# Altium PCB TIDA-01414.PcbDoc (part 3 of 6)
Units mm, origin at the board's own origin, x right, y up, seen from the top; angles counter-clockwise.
Board outline 400 x 135 mm, 4 copper layers (Top Copper, Copper Layer 2, Copper Layer 3, Bottom Copper), stack 1.567 mm thick; 835 components, 519 nets, 2420 pads, 2045 vias.
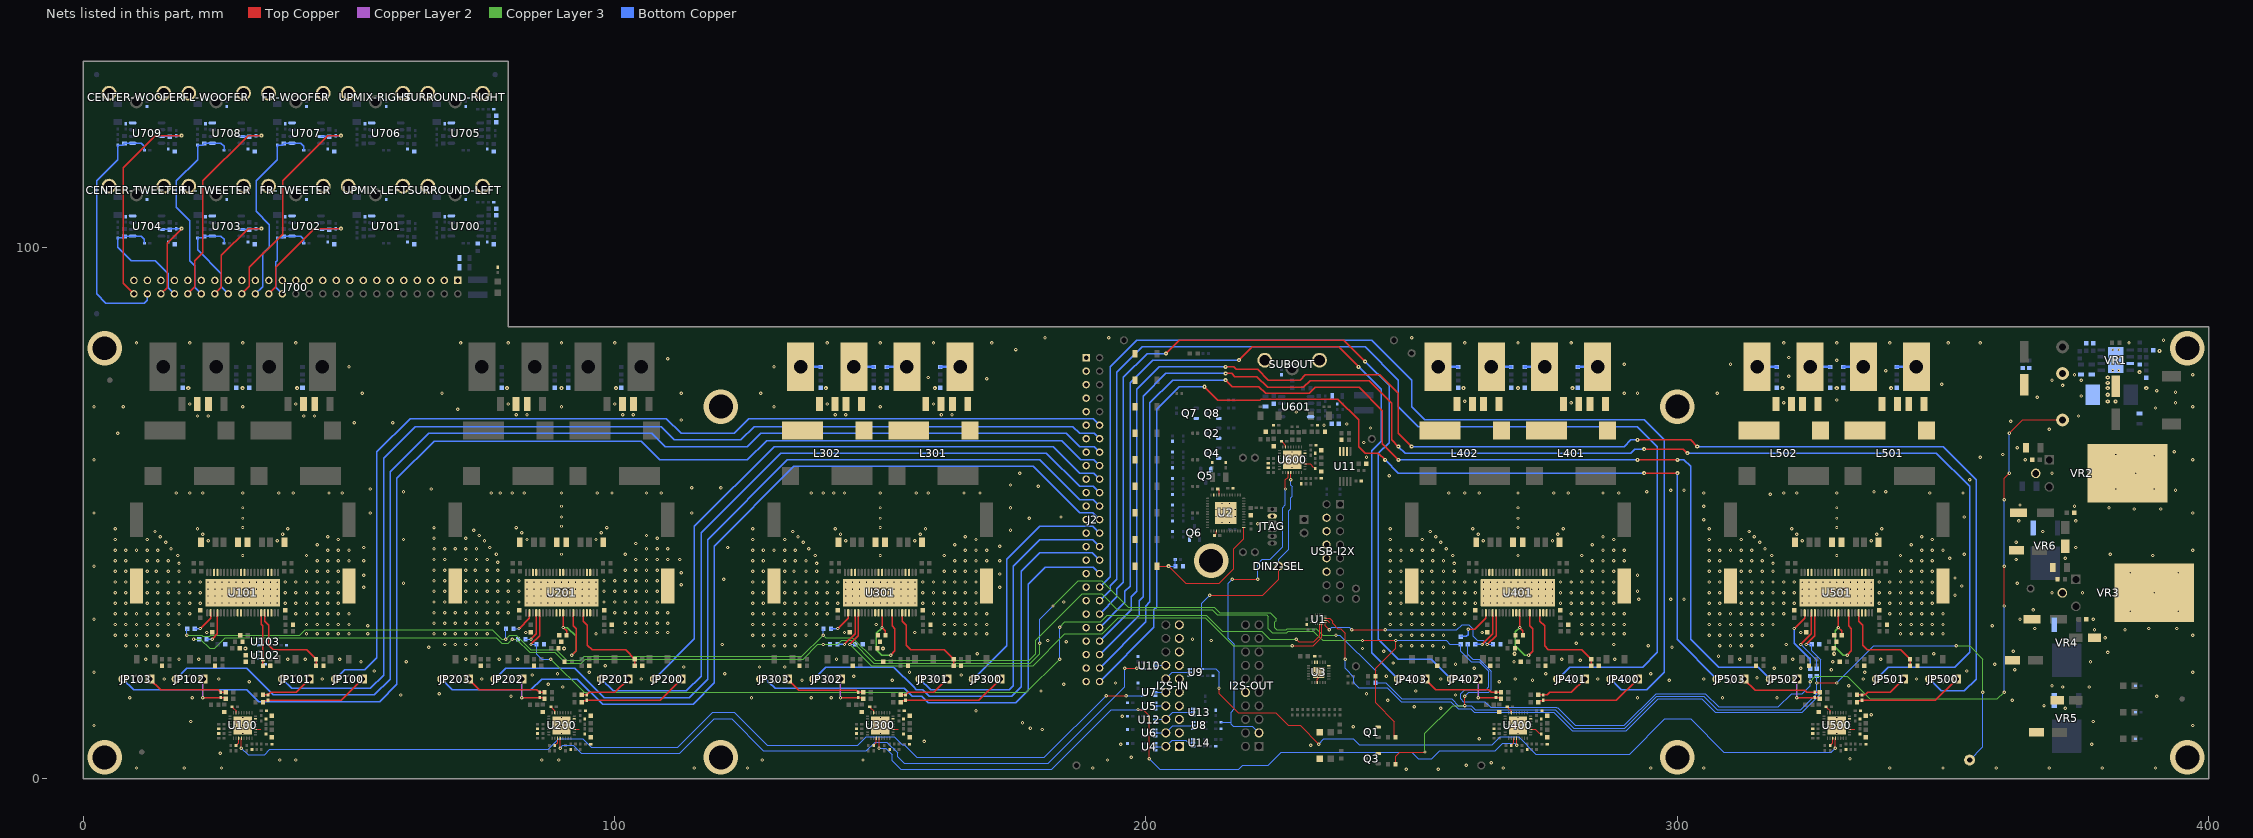
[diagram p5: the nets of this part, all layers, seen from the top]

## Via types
v1: diameter 0.635, hole 0.254, Top Copper to Bottom Copper, tented both sides, 1429 vias
v2: diameter 0.762, hole 0.254, Top Copper to Bottom Copper, tented both sides, 311 vias
v3: diameter 0.5, hole 0.2, Top Copper to Bottom Copper, 150 vias
v4: diameter 0.5, hole 0.2, Top Copper to Bottom Copper, tented both sides, 124 vias
v5: diameter 0.508, hole 0.254, Top Copper to Bottom Copper, tented both sides, 21 vias
v6: diameter 6.5, hole 4.5, Top Copper to Bottom Copper, tented both sides, 9 vias
v7: diameter 0.889, hole 0.254, Top Copper to Bottom Copper, tented both sides, 1 vias

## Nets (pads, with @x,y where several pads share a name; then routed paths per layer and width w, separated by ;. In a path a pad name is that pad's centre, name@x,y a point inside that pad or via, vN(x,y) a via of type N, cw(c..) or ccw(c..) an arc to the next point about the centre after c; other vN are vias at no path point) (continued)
\AMP-RESET2: R55.1 U1.3 U201.5 | length 174.4
  Top Copper w0.2: v1(228.25,26.25) 228.783,25.717 231.533,25.717 232.7,26.884 U1.3@232.7,29.2
  Top Copper w0.25: v1(84.25,25.25) 85.873,26.873 U201.5@85.873,31.2 U201.5@85.873,31.3
  Copper Layer 3 w0.2: v1(88,22.5) 94.25,16.25 177.5,16.25 v1(183.75,22.5) ; v1(183.75,28.5) 184.75,29.5 191.5,29.5 192.75,30.75 211.375,30.75 214.375,27.75 221.75,27.75 223.25,26.25 v1(228.25,26.25)
  Bottom Copper w0.2: v1(84.25,25.25) R55.1@85.3,25.25 85.3,23.45 86.25,22.5 v1(88,22.5) ; v1(183.75,22.5) v1(183.75,28.5)
\AMP-RESET3: R56.1 U1.4 U301.5 | length 107.4
  Top Copper w0.2: v1(227.5,25) 231.5,25 233.1,26.6 U1.4@233.1,29.2
  Top Copper w0.25: v1(144.25,25.25) 145.872,26.873 U301.5@145.872,31.2 U301.5@145.872,31.3
  Copper Layer 3 w0.2: v1(144.25,25.25) 148.25,21.25 178.75,21.25 184.75,27.25 191.75,27.25 194.75,30.25 211.125,30.25 216.375,25 v1(227.5,25)
  Bottom Copper w0.2: v1(144.25,25.25) R56.1@145.3,25.25
\AMP-RESET4: R57.1 U1.5 U401.5 | length 42.4
  Top Copper w0.2: U1.5@233.7,29.4 233.7,28.8 v1(234.5,28) ; v1(238.75,28) v1(245,28)
  Top Copper w0.25: v1(264.25,25.25) 265.873,26.873 U401.5@265.873,31.2 U401.5@265.873,31.3
  Bottom Copper w0.2: v1(234.5,28) 235,28.5 238.25,28.5 v1(238.75,28) ; v1(245,28) 258.5,28 259.5,29 260.75,29 261.625,28.125 261.625,26.75 262.375,26 263.5,26 v1(264.25,25.25) R57.1@265.3,25.25
\AMP-RESET5: R58.1 U1.7 U501.5 | length 129.5
  Top Copper w0.2: U1.7@233.7,30.2 234.55,30.2 235.125,29.625 235.125,29.25 236.125,28.25 236.625,28.25 237.5,27.375 v1(237.5,22.5)
  Top Copper w0.25: v1(324.25,25.25) 325.873,26.873 U501.5@325.873,31.2 U501.5@325.873,31.3
  Bottom Copper w0.2: v1(237.5,22.5) 237.5,20.75 239.125,19.125 239.125,18 240,17.125 245.375,17.125 248,14.5 257.375,14.5 258.75,13.125 261.125,13.125 261.75,12.5 276.75,12.5 280.25,9 290.375,9 296.375,15 304.625,15 307.125,12.5 323.5,12.5 327,16 327,22.375 325.3,24.075 R58.1@325.3,25.25 v1(324.25,25.25)
\CLIP_OTW: R19.1 R20.2 R21.1 R22.1 R23.1 R24.1 R25.1 TP2.1 | length 477.4
  Top Copper w0.2: v1(240.75,26) v1(247,26) 247,24.5 243.25,20.75 243.25,14.25 246.75,10.75 246.75,7.95 R20.2@246.95,7.75 ; v1(361.5,32.5) v1(361.5,40) ; v1(361.5,52.5) 361.5,56.5 v1(362.5,57.5) ; v1(362.5,65) 365,67.5 TP2.1@372.5,67.5
  Copper Layer 3 w0.2: v1(19.5,27) 22.25,27 22.5,26.75 23.75,26.75 24,27 40.75,27 41.75,28 77,28 78.75,26.25 v1(79.5,26.25) 80.25,27 81.5,27 84.25,24.25 89,24.25 91,22.25 93.5,22.25 94.25,23 135.25,23 v1(139.25,27) 139.75,26.5 144.75,26.5 149,22.25 178,22.25 179.25,23.5 179.25,26 188,34.75 191.625,34.75 194.625,31.75 212.5,31.75 213.438,30.812 222.687,30.812 223,30.5 223,28.25 223.75,27.5 226.5,27.5 226.75,27.75 231.5,27.75 233.25,26 v1(240.75,26) ; v1(325,18.25) 326,19.25 332,19.25 336.25,15 360.25,15 v1(361.5,16.25)
  Bottom Copper w0.2: v1(19.5,27) 19.5,28 R21.1@19.75,28.25 ; v1(79.5,26.25) 79.5,28.2 R22.1@79.55,28.25 ; v1(139.25,27) 139.25,28.2 R23.1@139.3,28.25 ; v1(247,26) 256.5,26 257.2,25.3 R24.1@259.25,25.3 259.25,24 261.25,22 262.684,22 264.5,20.184 264.5,17.25 264,16.75 260,16.75 259.25,16 259.25,15 259.75,14.5 263.75,14.5 264.85,13.4 277.166,13.4 277.266,13.3 277.45,13.3 280.75,10 290,10 296,16 305.25,16 307.75,13.5 319,13.5 321.5,16 323.5,16 325,17.5 v1(325,18.25) R25.1@325,19.3 ; v1(361.5,16.25) v1(361.5,32.5) ; v1(361.5,40) v1(361.5,52.5) ; v1(362.5,57.5) v1(362.5,65)
\CLIP_OTW1: R21.2 U101.2 | length 4.9
  Top Copper w0.25: v1(22,28.25) 23.968,30.218 U101.2@23.968,31.3
  Bottom Copper w0.25: R21.2@20.95,28.25 v1(22,28.25)
\CLIP_OTW2: R22.2 U201.2 | length 4.9
  Top Copper w0.25: v1(82,28.25) 83.968,30.218 U201.2@83.968,31.3
  Bottom Copper w0.2: R22.2@80.95,28.25 v1(82,28.25)
\CLIP_OTW3: R23.2 U301.2 | length 5.2
  Top Copper w0.25: v1(142,28.25) 143.967,30.218 U301.2@143.967,31.3
  Bottom Copper w0.25: R23.2@140.7,28.25 v1(142,28.25)
\CLIP_OTW4: R24.2 U401.2 | length 7.9
  Top Copper w0.25: v1(260.625,28.125) 261.875,28.125 263.968,30.218 U401.2@263.968,31.3
  Bottom Copper w0.25: R24.2@259.25,26.7 259.25,26.75 260.25,26.75 260.625,27.125 v1(260.625,28.125)
\CLIP_OTW5: R25.2 U501.2 | length 12.6
  Top Copper w0.25: v1(322,28.25) 323.968,30.218 U501.2@323.968,31.3
  Bottom Copper w0.25: v1(322,28.25) 322,25.5 325,22.5 R25.2@325,20.75
\FAULT: R27.1 R28.2 R29.1 R30.1 R31.1 R32.1 R33.1 TP1.1 | length 443.6
  Top Copper w0.2: R28.2@246.95,2.75 247,2.8 247,4.25 247.75,5 v1(252.5,5) ; v1(260,13.75) v1(260,15.5) ; v1(326.25,18) v1(330,18)
  Copper Layer 3 w0.2: v1(20.75,26.25) 22,26.25 23.75,24.5 24.75,24.5 26.75,26.5 77.75,26.5 78.75,25.5 80,25.5 v1(80.75,26.25) 81.5,26.25 84,23.75 88.75,23.75 90.75,21.75 93.75,21.75 94.5,22.5 135.5,22.5 138.25,25.25 v1(139.25,25.25) 142,25.25 142.75,26 144.5,26 148.75,21.75 178.25,21.75 180,23.5 v1(180,25.5) ; v1(182.5,32.5) 187.25,37.25 191.625,37.25 196.625,32.25 212.875,32.25 213.875,31.25 223.373,31.25 224.062,30.562 224.063,30.562 224.5,30.125 224.5,29.75 224.25,29.5 224.25,28.375 224.625,28 226.375,28 226.625,28.25 232,28.25 233.25,27 v1(235.75,27) ; v1(252.5,5) 252.5,8.5 257.75,13.75 v1(260,13.75) ; v1(352.5,25) 355,25 357.5,22.5 v1(357.5,16.25)
  Bottom Copper w0.2: v1(20.75,26.25) R29.1@21.8,26.25 R29.1@22,26.25 ; v1(80.75,26.25) R30.1@81.8,26.25 ; v1(139.25,25.25) R31.1@140.55,25.25 ; v1(180,25.5) 180,30 v1(182.5,32.5) ; v1(235.75,27) 236.5,27 243.2,20.3 R27.1@243.2,18 245.125,18 248.125,15 257.5,15 258.75,13.75 v1(260,13.75) 261.25,13.75 262,13 277,13 280.5,9.5 290.125,9.5 296.125,15.5 305,15.5 307.5,13 323.25,13 326.25,16 v1(326.25,18) R33.1@326.25,19.3 ; v1(260,15.5) 260.75,16.25 264.5,16.25 265,16.75 265,20.25 262.75,22.5 261.5,22.5 260.55,23.45 R32.1@260.55,25.25 ; v1(330,18) 337,25 v1(352.5,25) ; TP1.1@355,3.5 357.5,6 v1(357.5,16.25)
\FAULT1: R29.2 U101.4 | length 6.5
  Top Copper w0.25: v1(24.25,26.25) 25.238,27.238 U101.4@25.238,31.2 U101.4@25.238,31.3
  Bottom Copper w0.25: R29.2@23.2,26.25 v1(24.25,26.25)
\FAULT2: R30.2 U201.4 | length 6.5
  Top Copper w0.25: v1(84.25,26.25) 85.238,27.238 U201.4@85.238,31.2 U201.4@85.238,31.3
  Bottom Copper w0.2: R30.2@83.2,26.25 v1(84.25,26.25)
\FAULT3: R31.2 U301.4 | length 8.1
  Top Copper w0.25: v1(143.25,25.25) 145.237,27.238 U301.4@145.237,31.2 U301.4@145.237,31.3
  Bottom Copper w0.25: R31.2@142,25.25 v1(143.25,25.25)
\FAULT4: R32.2 U401.4 | length 8.2
  Top Copper w0.25: v1(263.25,25.25) 265.238,27.238 U401.4@265.238,31.2 U401.4@265.238,31.3
  Bottom Copper w0.25: R32.2@261.95,25.25 v1(263.25,25.25)
\FAULT5: R33.2 U501.4 | length 12.7
  Top Copper w0.25: v1(323.25,25.25) 325.238,27.238 U501.4@325.238,31.2 U501.4@325.238,31.3
  Bottom Copper w0.2: v1(323.25,25.25) 326.25,22.25 R33.2@326.25,20.7 R33.2@326.25,20.625
\RESET: C28.2 R74.1 RESET.1 U2.37 | length 28
  Top Copper w0.2: RESET.1@202.1,40 v2(204.25,40) 207.5,36.75 213.75,36.75 216.5,39.5 216.5,43.25 218.4,45.15 U2.37@218.4,47.25
  Bottom Copper w0.2: v2(204.25,40) C28.2@205.55,40 205.55,41.2 R74.1@205.5,41.25
BCK1: R75.1 U100.27 | length 1.6
  Top Copper w0.2: R75.1@28.75,6.25 29.25,6.75 U100.27@29.25,7.6
BCK2: R76.1 U200.27 | length 1.6
  Top Copper w0.2: R76.1@88.75,6.25 89.25,6.75 U200.27@89.25,7.6
BCK3: R77.1 U300.27 | length 1.6
  Top Copper w0.2: R77.1@148.75,6.25 149.25,6.75 U300.27@149.25,7.6
BCK4: R78.1 U400.27 | length 1.6
  Top Copper w0.2: R78.1@268.75,6.25 269.25,6.75 U400.27@269.25,7.6
BCK5: R79.1 U500.27 | length 1.6
  Top Copper w0.2: R79.1@328.75,6.25 329.25,6.75 U500.27@329.25,7.6
BCK6: I2S-OUT.3 R80.1 U600.27 | length 64.2
  Top Copper w0.2: v1(216.25,37.5) v1(221,37.5) ; v1(226.25,54.5) 226.25,56.25 226.75,56.75 U600.27@226.75,57.6
  Bottom Copper w0.2: R80.1@214.125,10.625 216,10.625 ; v1(216.25,37.5) 215.5,36.75 215.5,26.375 216.625,25.25 216.625,13.125 216,12.5 216,10.25 216.375,9.875 220.005,9.875 I2S-OUT.3@221.27,8.61 ; v1(221,37.5) 221,40.375 221.875,41.25 223.375,41.25 225.75,43.625 225.75,51 226.25,51.5 v1(226.25,54.5)
CENTERTWEETER+: C515.1 C516.1 CT+.1 L501.2 | length 3.8
  Bottom Copper w0.5: C516.1@341.25,77.45 341.3,77.5 CT+.1@345,77.5
CENTERTWEETER-: C526.1 C527.1 CT-.1 L501.3 | length 3.8
  Bottom Copper w0.5: C527.1@331.25,77.45 331.3,77.5 CT-.1@335,77.5
CENTERWOOFER+: C535.1 C536.1 CW+.1 L502.2 | length 3.8
  Bottom Copper w0.5: CW+.1@325,77.5 328.7,77.5 C536.1@328.75,77.45
CENTERWOOFER-: C540.1 C541.1 CW-.1 L502.3 | length 3.8
  Bottom Copper w0.5: CW-.1@315,77.5 318.7,77.5 C541.1@318.75,77.45
CT+: C731.2 J700.44 R704.1 R714.1 U704.1 | length 23.7
  Bottom Copper w0.25: R714.1@11.5,100.75 11.5,101.5 10.905,102.095 U704.1@9.275,102.095 7.795,102.095 7.45,101.75 R704.1@6.5,101.75 6.5,100 9,97.5 13.5,97.5 16,95 16,92.37 J700.44@17.14,91.23
CT-: C741.2 J700.46 R719.1 U704.7 | length 17.8
  Top Copper w0.25: J700.46@14.6,91.23 15.75,92.38 15.75,100.75 v2(18.5,103.5)
  Bottom Copper w0.25: U704.7@14.725,103.365 16.185,103.365 C741.2@16.25,103.3 16.45,103.5 R719.1@17.5,103.5 v2(18.5,103.5)
CW+: C746.2 J700.48 R724.1 R734.1 U709.1 | length 47.5
  Bottom Copper w0.25: R734.1@11.5,118.25 11.5,119 10.905,119.595 7.795,119.595 7.45,119.25 R724.1@6.5,119.25 6.5,116.5 2.5,112.5 2.5,91.25 4.25,89.5 11.5,89.5 12.06,90.06 J700.48@12.06,91.23
CW-: C756.2 J700.50 R739.1 U709.7 | length 42
  Top Copper w0.25: J700.50@9.52,91.23 7.5,93.25 7.5,115 13.5,121 v2(18.5,121)
  Bottom Copper w0.25: U709.7@14.725,120.865 16.185,120.865 C756.2@16.25,120.8 16.45,121 v2(18.5,121)
DAC1L+: C117.1 JP100.1 R101.2 | length 20.5
  Top Copper w0.25: R101.2@33.825,14.375 34.075,14.625 34.625,14.625 C117.1@34.75,14.75 48.54,14.75 JP100.1@52.54,18.75
DAC1L-: C117.2 JP101.1 R103.2 | length 10
  Top Copper w0.25: R103.2@33.825,15.75 C117.2@34.75,15.75 35.25,16.25 40.04,16.25 JP101.1@42.54,18.75
DAC1R+: C121.2 JP102.1 R107.2 | length 7.9
  Top Copper w0.25: v1(22.5,15.25) C121.2@25.875,15.25 26.55,15.25 R107.2@26.8,15
  Copper Layer 2 w0.25: v1(22.5,15.25) JP102.1@22.5,18.71
  Bottom Copper w0.25: JP102.1@22.5,18.71 JP102.1@22.54,18.75
DAC1R-: C121.1 JP103.1 R105.2 | length 15.3
  Top Copper w0.25: JP103.1@12.54,18.75 14.54,16.75 25.375,16.75 C121.1@25.875,16.25 R105.2@26.8,16.25
DAC2L+: C217.1 JP200.1 R201.2 | length 20.5
  Top Copper w0.25: R201.2@93.825,14.375 94.075,14.625 94.625,14.625 C217.1@94.75,14.75 108.54,14.75 JP200.1@112.54,18.75
DAC2L-: C217.2 JP201.1 R203.2 | length 10
  Top Copper w0.25: R203.2@93.825,15.75 C217.2@94.75,15.75 95.25,16.25 100.04,16.25 JP201.1@102.54,18.75
DAC2R+: C221.2 JP202.1 R207.2 | length 7.9
  Top Copper w0.25: v1(82.5,15.25) C221.2@85.875,15.25 86.55,15.25 R207.2@86.8,15
  Copper Layer 2 w0.25: v1(82.5,15.25) JP202.1@82.5,18.71
  Bottom Copper w0.25: JP202.1@82.5,18.71 JP202.1@82.54,18.75
DAC2R-: C221.1 JP203.1 R205.2 | length 15.3
  Top Copper w0.25: JP203.1@72.54,18.75 74.54,16.75 85.375,16.75 C221.1@85.875,16.25 R205.2@86.8,16.25
DAC3L+: C317.1 JP300.1 R301.2 | length 20.5
  Top Copper w0.25: R301.2@153.825,14.375 154.075,14.625 154.625,14.625 C317.1@154.75,14.75 168.54,14.75 JP300.1@172.54,18.75
DAC3L-: C317.2 JP301.1 R303.2 | length 10
  Top Copper w0.25: R303.2@153.825,15.75 C317.2@154.75,15.75 155.25,16.25 160.04,16.25 JP301.1@162.54,18.75
DAC3R+: C321.2 JP302.1 R307.2 | length 7.9
  Top Copper w0.25: v1(142.5,15.25) C321.2@145.875,15.25 146.55,15.25 R307.2@146.8,15
  Copper Layer 2 w0.25: v1(142.5,15.25) JP302.1@142.5,18.71
  Bottom Copper w0.25: JP302.1@142.5,18.71 JP302.1@142.54,18.75
DAC3R-: C321.1 JP303.1 R305.2 | length 15.3
  Top Copper w0.25: JP303.1@132.54,18.75 134.665,16.625 145.5,16.625 C321.1@145.875,16.25 R305.2@146.8,16.25
DAC4L+: C417.1 JP400.1 R401.2 | length 20.5
  Top Copper w0.25: R401.2@273.825,14.375 274.075,14.625 274.625,14.625 C417.1@274.75,14.75 288.54,14.75 JP400.1@292.54,18.75
DAC4L-: C417.2 JP401.1 R403.2 | length 10
  Top Copper w0.25: R403.2@273.825,15.75 C417.2@274.75,15.75 275.375,15.75 275.5,15.75 276,16.25 280.04,16.25 JP401.1@282.54,18.75
DAC4R+: C421.2 JP402.1 R407.2 | length 7.9
  Top Copper w0.25: v1(262.5,15.25) C421.2@265.875,15.25 266.55,15.25 R407.2@266.8,15
  Copper Layer 2 w0.25: v1(262.5,15.25) JP402.1@262.5,18.71
  Bottom Copper w0.25: JP402.1@262.5,18.71 JP402.1@262.54,18.75
DAC4R-: C421.1 JP403.1 R405.2 | length 15.3
  Top Copper w0.25: JP403.1@252.54,18.75 254.54,16.75 264.5,16.75 265,16.25 C421.1@265.875,16.25 R405.2@266.8,16.25
DAC5L+: C517.1 JP500.1 R501.2 | length 20.5
  Top Copper w0.25: R501.2@333.825,14.375 334.075,14.625 334.625,14.625 C517.1@334.75,14.75 348.54,14.75 JP500.1@352.54,18.75
DAC5L-: C517.2 JP501.1 R503.2 | length 10
  Top Copper w0.25: R503.2@333.825,15.75 C517.2@334.75,15.75 335.375,15.75 335.875,16.25 340.04,16.25 JP501.1@342.54,18.75
DAC5R+: C521.2 JP502.1 R507.2 | length 7.9
  Top Copper w0.25: v1(322.5,15.25) C521.2@325.875,15.25 326.55,15.25 R507.2@326.8,15
  Copper Layer 2 w0.25: v1(322.5,15.25) JP502.1@322.5,18.71
  Bottom Copper w0.25: JP502.1@322.5,18.71 JP502.1@322.54,18.75
DAC5R-: C521.1 JP503.1 R505.2 | length 15.3
  Top Copper w0.25: JP503.1@312.54,18.75 314.665,16.625 324,16.625 324.375,16.25 C521.1@325.875,16.25 R505.2@326.8,16.25
DIN0: U5.4 U300.28 U400.28 | length 150.8
  Top Copper w0.2: v1(149.75,5.75) U300.28@149.75,7.6 ; v1(198.5,13) 199.5,13 200.625,11.875 v1(200.625,3.75) ; v1(269.75,6.25) U400.28@269.75,7.6
  Bottom Copper w0.2: v1(149.75,5.75) 151,5.75 152.25,4.5 152.25,3.375 153.875,1.75 182.25,1.75 193.5,13 v1(198.5,13) 195.05,13 195.025,12.975 U5.4@199.5,12.975 ; v1(200.625,3.75) 202.625,1.75 217.5,1.75 218.25,2.5 223,2.5 225.5,5 250,5 251.25,3.75 253.75,3.75 255.25,5.25 265.75,5.25 267.125,6.625 269.375,6.625 v1(269.75,6.25)
DIN1: U7.4 U100.28 | length 186.5
  Top Copper w0.2: v1(29.75,5.75) U100.28@29.75,7.6 ; v1(192.5,15.625) v1(196.25,15.625)
  Bottom Copper w0.2: v1(29.75,5.75) 31,4.5 34.123,4.5 35.123,5.5 87.5,5.5 89.5,7.5 94,7.5 95.625,5.875 111.875,5.875 118.5,12.5 122.5,12.5 128.75,6.25 145.75,6.25 147.375,7.875 152.625,7.875 154.125,6.375 154.5,6.375 156.875,4 180.875,4 v1(192.5,15.625) ; v1(196.25,15.625) 199.475,15.625 U7.4@199.5,15.6
DIN2: DIN2-SEL.2 U9.4 U500.28 U600.28 | length 187.7
  Top Copper w0.2: v1(212,34.5) 222,34.5 225,37.5 DIN2-SEL.2@225,40 ; v1(213.75,17) 213.75,16 217.375,12.375 224.375,12.375 226.75,10 229,10 v1(232.5,6.5) ; v1(227.25,56.25) U600.28@227.25,57.6 ; v1(329.75,5.75) U500.28@329.75,7.6
  Bottom Copper w0.2: v1(212,34.5) 210.5,33 U9.4@210.5,20.65 213.1,20.65 213.75,20 v1(213.75,17) ; DIN2-SEL.2@225,40 225,41.25 226.875,43.125 226.875,50.375 227.25,50.75 227.25,52.875 227.5,53.125 227.5,55 227.25,55.25 v1(227.25,56.25) ; v1(232.5,6.5) 233.5,7.5 239,7.5 240.125,6.375 265.125,6.375 266.625,7.875 270.125,7.875 273.375,4.625 291,4.625 297.625,11.25 302.5,11.25 308.75,5 329,5 v1(329.75,5.75)
DIN3: U10.4 U200.28 | length 129.9
  Top Copper w0.2: v1(89.75,5.75) U200.28@89.75,7.6 ; v1(196,20.75) v1(198.25,20.75)
  Bottom Copper w0.2: v1(89.75,5.75) 90.25,6.25 92.25,6.25 93.75,4.75 112.25,4.75 118.75,11.25 122,11.25 128,5.25 147.375,5.25 149,6.875 151.25,6.875 153.25,4.875 153.25,4.125 154.5,2.875 181.625,2.875 196,17.25 v1(196,20.75) ; v1(198.25,20.75) 199.325,20.75 U10.4@199.475,20.6
DSP-BCLK: I2S-IN.4 U6.2 U8.2 | length 7.7
  Bottom Copper w0.2: U6.2@201.75,8.625 I2S-IN.4@203.715,8.625 ; I2S-IN.4@203.73,8.61 205.08,9.96 208.875,9.96 U8.2@208.875,10
DSP-DATA0: I2S-IN.8 U5.2 | length 2
  Bottom Copper w0.2: U5.2@201.75,13.625 201.815,13.69 I2S-IN.8@203.73,13.69
DSP-DATA1: I2S-IN.10 U7.2 | length 2
  Bottom Copper w0.2: U7.2@201.75,16.25 201.77,16.23 I2S-IN.10@203.73,16.23
DSP-DATA2: I2S-IN.12 U9.2 | length 5
  Bottom Copper w0.2: I2S-IN.12@203.73,18.77 204.96,20 U9.2@208.25,20
DSP-DATA3: I2S-IN.14 U10.2 | length 2
  Bottom Copper w0.2: U10.2@201.725,21.25 201.785,21.31 I2S-IN.14@203.73,21.31
DSP-LRCLK: I2S-IN.2 U4.2 U14.2 | length 7.8
  Bottom Copper w0.2: U4.2@201.75,6 I2S-IN.2@203.66,6 ; I2S-IN.2@203.73,6.07 204.91,7.25 207.5,7.25 208,6.75 U14.2@208.875,6.75
DSP-MCLK: I2S-IN.6 U12.2 U13.2 | length 7.7
  Bottom Copper w0.2: U12.2@201.75,11.125 201.775,11.15 I2S-IN.6@203.73,11.15 205.08,12.5 U13.2@208.875,12.5
DVDD2: C232.2 U201.12 U201.15 | length 20
  Top Copper w0.25: v1(90.318,28.433) 90.95,27.8 C232.2@90.95,27 ; v1@90.318,28.5 U201.12@90.318,31.2 ; v1(91.95,23.25) 92.75,24.05 92.75,28.25 92.223,28.778 U201.15@92.223,31.3
  Copper Layer 3 w0.25: v1(90.318,28.433) 91.067,28.433 92.75,26.75 92.75,24.05 v1(91.95,23.25)
DVDD3: C332.2 U301.12 U301.15 | length 20.7
  Top Copper w0.25: v1(150.317,28.433) 150.95,27.8 C332.2@150.95,27 ; v1@150.317,28.5 U301.12@150.317,31.2 ; v1(151.95,23.25) 152.75,24.05 152.75,28.25 152.222,28.778 U301.15@152.222,31.3
  Copper Layer 3 w0.25: v1(150.317,28.433) 149.25,27.365 149.25,24.25 150.25,23.25 v1(151.95,23.25)
DVDD4: C432.2 U401.12 U401.15 | length 20
  Top Copper w0.25: v1(270.318,28.433) 270.95,27.8 C432.2@270.95,27 ; v1@270.318,28.5 U401.12@270.318,31.2 ; v1@271.95,23.25 v1@271.975,23.275 ; v1(272,23.25) 272.75,24 272.75,28.25 272.223,28.778 U401.15@272.223,31.3
  Copper Layer 3 w0.25: v1(270.318,28.433) 269.5,27.615 269.5,25 271.25,23.25 v1(272,23.25)
DVDD5: C532.2 U501.12 U501.15 | length 19.7
  Top Copper w0.25: v1(330.318,28.433) 330.95,27.8 C532.2@330.95,27 ; v1@330.318,28.5 U501.12@330.318,31.2 ; v1(331.95,23.25) 332.75,24.05 332.75,28.25 332.223,28.778 U501.15@332.223,31.3
  Copper Layer 3 w0.25: v1(330.318,28.433) 329.75,27.865 329.75,24.75 331.25,23.25 v1(331.95,23.25)
FLT+: C730.2 J700.36 R703.1 R713.1 U703.1 | length 19.1
  Bottom Copper w0.25: R713.1@26.5,100.75 26.5,101.5 25.905,102.095 22.795,102.095 C730.2@22.75,102.05 22.45,101.75 R703.1@21.5,101.75 21.5,99.5 26,95 26,92.53 J700.36@27.3,91.23
FLT-: C740.2 J700.38 R718.1 U703.7 | length 21.2
  Top Copper w0.25: J700.38@24.76,91.23 26,92.47 26,98.5 31,103.5 v2(33.5,103.5)
  Bottom Copper w0.25: U703.7@29.725,103.365 31.185,103.365 C740.2@31.25,103.3 31.45,103.5 R718.1@32.5,103.5 v2(33.5,103.5)
FLW+: C745.2 J700.40 R723.1 R733.1 U708.1 | length 37.8
  Bottom Copper w0.25: J700.40@22.22,91.23 21,92.45 21,96.5 20,97.5 20,105 17.5,107.5 17.5,112.5 21.5,116.5 R723.1@21.5,119.25 22.45,119.25 22.795,119.595 25.905,119.595 26.5,119 R733.1@26.5,118.25
FLW-: C755.2 J700.42 R738.1 U708.7 | length 40.8
  Top Copper w0.25: J700.42@19.68,91.23 21,92.55 21,97.5 22.5,99 22.5,112.5 31,121 v2(33.5,121)
  Bottom Copper w0.25: U708.7@29.725,120.865 31.185,120.865 C755.2@31.25,120.8 31.45,121 v2(33.5,121)
FRONTLEFTTWEETER+: C415.1 C416.1 FLT+.1 L401.2 | length 3.8
  Bottom Copper w0.5: C416.1@281.25,77.45 281.3,77.5 FLT+.1@285,77.5
FRONTLEFTTWEETER-: C426.1 C427.1 FLT-.1 L401.3 | length 3.8
  Bottom Copper w0.5: C427.1@271.25,77.45 271.3,77.5 FLT-.1@275,77.5
FRONTLEFTWOOFER+: C435.1 C436.1 FLW+.1 L402.2 | length 3.8
  Bottom Copper w0.5: FLW+.1@265,77.5 268.7,77.5 C436.1@268.75,77.45
FRONTLEFTWOOFER-: C440.1 C441.1 FLW-.1 L402.3 | length 3.8
  Bottom Copper w0.5: FLW-.1@255,77.5 258.7,77.5 C441.1@258.75,77.45
FRONTRIGHTTWEETER+: C315.1 C316.1 FRT+.1 L301.2 | length 3.8
  Bottom Copper w0.5: C316.1@161.25,77.45 161.3,77.5 FRT+.1@165,77.5
FRONTRIGHTTWEETER-: C326.1 C327.1 FRT-.1 L301.3 | length 3.8
  Bottom Copper w0.5: C327.1@151.25,77.45 151.3,77.5 FRT-.1@155,77.5
FRONTRIGHTWOOFER+: C335.1 C336.1 FRW+.1 L302.2 | length 3.8
  Bottom Copper w0.5: FRW+.1@145,77.5 148.7,77.5 C336.1@148.75,77.45
FRONTRIGHTWOOFER-: C340.1 C341.1 FRW-.1 L302.3 | length 3.8
  Bottom Copper w0.5: FRW-.1@135,77.5 138.7,77.5 C341.1@138.75,77.45
FRT+: C729.2 J700.28 R702.1 R712.1 U702.1 | length 17.3
  Bottom Copper w0.25: J700.28@37.46,91.23 36.25,92.44 36.25,97.25 36.5,97.5 R702.1@36.5,101.75 37.45,101.75 37.795,102.095 U702.1@39.275,102.095 40.905,102.095 41.5,101.5 R712.1@41.5,100.75
FRT-: C739.2 J700.30 R717.1 U702.7 | length 24.7
  Top Copper w0.25: J700.30@34.92,91.23 36.25,92.56 36.25,96.25 43.5,103.5 v2(48.5,103.5)
  Bottom Copper w0.25: U702.7@44.725,103.365 46.185,103.365 C739.2@46.25,103.3 46.45,103.5 R717.1@47.5,103.5 v2(48.5,103.5)
FRW+: C744.2 J700.32 R722.1 R732.1 U707.1 | length 37.9
  Bottom Copper w0.25: J700.32@32.38,91.23 33.75,92.6 33.75,98.75 35,100 35,104.25 32.5,106.75 32.5,112.5 36.5,116.5 R722.1@36.5,119.25 37.45,119.25 37.795,119.595 40.905,119.595 41.5,119 R732.1@41.5,118.25
FRW-: C754.2 J700.34 R737.1 U707.7 | length 42.8
  Top Copper w0.25: J700.34@29.84,91.23 31.25,92.64 31.25,96.25 37.5,102.5 37.5,112.5 46,121 v2(48.5,121)
  Bottom Copper w0.25: U707.7@44.725,120.865 46.185,120.865 C754.2@46.25,120.8 46.45,121 v2(48.5,121)
GND: C3.2 C4.2 C5.2 C6.1 C7.2 C8.2 C9.2 C10.2 C11.2 C12.2 C13.2 C14.2 C15.2 C16.1 C17.2 C18.2 C19.2 C20.2 C21.2 C22.1 C23.2 C24.2 C25.2 C26.2 C27.2 C28.1 C29.1 C30.1 C31.1 C32.1 C33.1 C34.1 C35.1 C36.1 C37.1 C38.1 C43.1 C44.1 C45.1 C46.1 C48.2 C49.2 C50.2 C51.2 C52.1 C53.2 C55.1 C56.1 C57.2 C58.1 C59.1 C100.2 C101.2 C102.1 C103.1 C104.2 C105.2 C106.2 C107.2 C108.2 C109.2 C111.2 C112.2 C113.1 C114.1 C115.2 C118.2 C124.2 C125.2 C126.2 C128.2 C130.2 C131.2 C132.1 C133.1 C135.2 C137.2 C140.2 C142.1 C143.2 C144.1 C145.1 C200.2 C201.2 C202.1 C203.1 C204.2 C205.2 C206.2 C207.2 C208.2 C209.2 C211.2 C212.2 C213.1 C214.1 C215.2 C218.2 C224.2 C225.2 C226.2 C228.2 C230.2 C231.2 C232.1 C233.1 C235.2 C237.2 C240.2 C242.1 C243.2 C300.2 C301.2 C302.1 C303.1 C304.2 C305.2 C306.2 C307.2 C308.2 C309.2 C311.2 C312.2 C313.1 C314.1 C315.2 C318.2 C324.2 C325.2 C326.2 C328.2 C330.2 C331.2 C332.1 C333.1 C335.2 C337.2 C340.2 C342.1 C343.2 C400.2 C401.2 C402.1 C403.1 C404.2 C405.2 C406.2 C407.2 C408.2 C409.2 C411.2 C412.2 C413.1 C414.1 C415.2 C418.2 C424.2 C425.2 C426.2 C428.2 C430.2 C431.2 C432.1 C433.1 C435.2 C437.2 C440.2 C442.1 C443.2 C500.2 C501.2 C502.1 C503.1 C504.2 C505.2 C506.2 C507.2 C508.2 C509.2 C511.2 C512.2 C513.1 C514.1 C515.2 C518.2 C524.2 C525.2 C526.2 C528.2 C530.2 C531.2 C532.1 C533.1 C535.2 C537.2 C540.2 C542.1 C543.2 C601.2 C602.2 C603.2 C604.2 C605.2 C606.2 C607.2 C612.2 C613.2 C614.1 C615.1 C616.2 C617.2 C618.2 C619.2 D12.2 FAULT.2 GND-IN.1 I2S-IN.1 I2S-IN.3 I2S-IN.5 I2S-IN.7 I2S-IN.9 I2S-IN.11 I2S-IN.13 I2S-IN.15 I2S-IN.17 I2S-IN.19 I2S-OUT.10 J2.1 J2.3 J2.5 J2.7 J2.9 J2.11 J2.13 J2.15 J2.17 J2.19 J2.21 J2.23 J2.25 J2.27 J2.29 J2.31 J2.33 J2.35 J2.37 J2.39 J2.41 J2.43 J2.45 J2.47 J2.49 JTAG.2 LOAD.1 MODE1.1 MODE2.1 MODE3.1 MODE4.1 MUTE.1 OTW.2 Q1.2 Q2.2 Q3.2 Q4.2 Q5.2 Q6.2 Q7.2 Q8.2 R1.1 R2.2 R17.1 R37.1 R47.1 R48.1 R51.2 R52.2 R53.2 R54.2 R55.2 R56.2 R57.2 R58.2 R94.2 R104.1 R109.1 R113.1 R114.1 R115.2 R118.1 R119.1 R120.1 R204.1 R209.1 R213.1 R214.1 R215.2 R218.1 R219.1 R220.1 R304.1 R309.1 R313.1 R314.1 R315.2 R318.1 R319.1 R320.1 R404.1 R409.1 R413.1 R414.1 R415.2 R418.1 R419.1 R420.1 R504.1 R509.1 R513.1 R514.1 R515.2 R518.1 R519.1 R520.1 R611.2 R615.1 R616.1 R617.2 R619.1 R620.1 RESET.2 SUBOUT.2 SUBOUT.3 U1.6 U1.16 U2.9 U2.11 U2.27 U2.49 U3.9 U3.18 U3.22 U3.23 U3.25@232.5,20 U4.1 U4.3 U5.1 U5.3 U6.1 U6.3 U7.1 U7.3 U8.1 U8.3 U9.1 U9.3 U10.1 U10.3 U11.2 U11.3 U11.4 U12.1 U12.3 U13.1 U13.3 U14.1 U14.3 U100.3 U100.7 U100.15 U100.33 U101.10 U101.11 U101.19 U101.20 U101.25 U101.26 U101.33 U101.34 U101.41 U101.42 U101.45@30,35 U102.1 U102.3 U103.1 U103.3 U200.3 U200.7 U200.15 U200.33 U201.10 U201.11 U201.19 U201.20 U201.25 U201.26 U201.33 U201.34 U201.41 U201.42 U201.45@90,35 U300.3 U300.7 U300.15 U300.33 U301.10 U301.11 U301.19 U301.20 U301.25 U301.26 U301.33 U301.34 U301.41 U301.42 U301.45@150,35 U400.3 U400.7 U400.15 U400.33 U401.10 U401.11 U401.19 U401.20 U401.25 U401.26 U401.33 U401.34 U401.41 U401.42 U401.45@270,35 U500.3 U500.7 U500.15 U500.33 U501.10 U501.11 U501.19 U501.20 U501.25 U501.26 U501.33 U501.34 U501.41 U501.42 U501.45@330,35 U600.3 U600.7 U600.15 U600.33 U601.4 USB-I2X.4 USB-I2X.6 USB-I2X.8 USB-I2X.10 USB-I2X.12 VOL-DN.1 VOL-UP.1 VR1.7 VR1.9@382.5,78.75 VR2.2 VR3.2 VR4.1 VR5.1 VR6.1 | length 19.6
  Top Copper w0.2: C105.2@28.125,13.375 28.75,12.75 U100.15@28.75,12.4 ; U100.3@32.4,9.25 33.375,9.25 ; C205.2@88.125,13.375 88.75,12.75 U200.15@88.75,12.4 ; U200.3@92.4,9.25 93.375,9.25 ; C305.2@148.125,13.375 148.75,12.75 U300.15@148.75,12.4 ; U300.3@152.4,9.25 153.375,9.25 ; C32.1@212.875,45.75 213.25,46.125 U2.27@213.25,46.6 ; C34.1@213.625,54.5 213.75,54.375 U2.9@213.75,53.4 ; C602.2@225.625,63.375 226.25,62.75 U600.15@226.25,62.4 ; U600.3@229.9,59.25 230.875,59.25 231.5,58.625 ; U3.9@232.25,18.1 232.25,18.75 U3.25@232.5,19 ; U1.6@233.7,29.8 234.124,29.8 234.5,29.424 ; C405.2@268.125,13.5 268.125,13.375 268.75,12.75 U400.15@268.75,12.4 ; U400.3@272.4,9.25 273.25,9.25 274,8.5 C409.2@274.25,8.5 ; C505.2@328.125,13.375 328.75,12.75 U500.15@328.75,12.4 ; U500.3@332.4,9.25 333.375,9.25
  other v1: 249,1.75 255,1.75 10,2 19,2 26,2 115,2 125,2 190,2 267.25,2 295,2 305,2 340,2 350,2 360,2 370,2 380,2 390,2 260.25,2.5 265,3 37,3.5 40,3.5 86.25,3.5 89.5,3.5 127.75,3.5 146.75,3.5 192.75,3.5 332.5,3.75 197.25,4 25.75,4.75 231,6.25 195.25,6.5 378,6.5 158.25,7 262.75,7.5 180.5,9.25 178.25,9.5 239,9.75 2,10 397,10 176.75,10.5 20.25,10.75 378.25,10.75 195.5,11.75 336.5,12 168,12.75 255.5,13.25 373,13.25 250.5,13.5 369,13.75 245.5,14.75 363,14.75 8.75,15.25 20.5,15.25 125.75,15.25 137,15.25 140.75,15.25 292.5,15.25 308.5,15.25 318.75,15.25 80.5,15.5 390.25,15.5 59.75,15.75 258.25,15.75 67,16 241.5,16 180.25,16.5 250.75,16.5 90.25,17.25 372.5,17.25 377.5,17.25 332.25,17.5 370.5,17.5 87.5,17.75 184.5,17.75 194.25,18 31.25,18.25 266.5,18.25 135.25,18.5 152.25,18.5 272.75,18.5 298.5,18.5 15.25,18.75 25.5,18.75 45,18.75 75,18.75 105,18.75 255.5,18.75 269.5,18.75 285,18.75 305,18.75 335,18.75 345,18.75 315,19 145,19.25 245.25,19.25 84.5,19.5 165.25,19.5 89.25,19.75 120.75,19.75 275.25,19.75 295,19.75 2,20 95.25,20 155.5,20 335.25,20 397,20 54.75,20.25 354.5,20.25 329,20.5 363.5,20.5 261.75,20.75 318.25,20.75 323.25,20.75 113,21 127.25,21 132,21 98.25,21.25 258.25,21.5 359.75,21.5 246.5,21.75 52.25,22 60.75,22 269.25,22 329.25,22 377.75,22 281.75,22.25 11.75,22.5 18,22.5 21.75,22.5 38.5,22.5 41.75,22.5 48.25,22.5 72,22.5 78.25,22.5 81.75,22.5 141.75,22.5 278.25,22.5 288.25,22.5 311.75,22.5 321.75,22.5 338.25,22.5 307.75,23 168.25,23.5 348.25,23.5 381,23.75 244.75,24 363.25,24 240.75,24.5 65,24.75 256,24.75 299,24.75 8,25 10,25 12,25 14,25 128,25 130,25 132,25 134,25 248,25 250,25 252,25 254,25 294.5,25 308,25 310,25 312,25 314,25 68,25.25 70,25.25 72,25.25 74,25.25 120.25,25.25 288,25.25 320.5,25.25 281,25.5 185,25.75 181.5,26 212.25,26 208.75,26.25 380.5,26.5 6,27 8,27 10,27 12,27 14,27 16,27 126,27 128,27 130,27 132,27 134,27 136,27 246,27 248,27 250,27 252,27 254,27 256,27 306,27 308,27 310,27 312,27 314,27 316,27 397,27 42,27.25 44,27.25 46,27.25 48,27.25 50,27.25 53.5,27.25 66,27.25 68,27.25 70,27.25 72,27.25 74,27.25 76,27.25 96.5,27.25 162,27.25 164,27.25 166,27.25 168,27.25 170,27.25 282,27.25 284,27.25 286,27.25 288,27.25 290,27.25 342,27.25 344,27.25 346,27.25 348,27.25 350,27.25 23.25,27.5 83.25,27.5 102,27.5 104,27.5 106,27.5 108,27.5 110,27.5 143.25,27.5 156.5,27.5 263.25,27.5 323.25,27.5 378.5,28 384.25,28 367.25,28.25 388.75,28.25 394,28.25 53.5,28.75 359.25,28.75 6,29 8,29 10,29 12,29 14,29 16,29 18,29 42,29 44,29 46,29 48,29 50,29 126,29 128,29 130,29 132,29 134,29 136,29 138,29 149.25,29 162,29 164,29 166,29 168,29 170,29 246,29 248,29 250,29 252,29 254,29 256,29 258,29 282,29 284,29 286,29 288,29 290,29 306,29 308,29 310,29 312,29 314,29 316,29 318,29 342,29 344,29 346,29 348,29 350,29 66,29.25 68,29.25 70,29.25 72,29.25 74,29.25 76,29.25 78,29.25 102,29.25 104,29.25 106,29.25 108,29.25 110,29.25 2,30 364.5,30 378.25,30 6,31 8,31 10,31 12,31 14,31 16,31 18,31 20,31 40,31 42,31 44,31 46,31 48,31 50,31 126,31 128,31 130,31 132,31 134,31 136,31 138,31 140,31 160,31 162,31 164,31 166,31 168,31 170,31 246,31 248,31 250,31 252,31 254,31 256,31 258,31 260,31 280,31 282,31 284,31 286,31 288,31 290,31 306,31 308,31 310,31 312,31 314,31 316,31 318,31 320,31 340,31 342,31 344,31 346,31 348,31 350,31 66,31.25 68,31.25 70,31.25 72,31.25 74,31.25 76,31.25 78,31.25 80,31.25 100,31.25 102,31.25 104,31.25 106,31.25 108,31.25 110,31.25 385.25,31.5 394.25,31.5 367,31.75 6,33 8,33 12,33 14,33 16,33 18,33 20,33 22,33 38,33 40,33 42,33 44,33 46,33 48,33 126,33 128,33 132,33 134,33 136,33 138,33 140,33 142,33 158,33 160,33 162,33 164,33 166,33 168,33 246,33 248,33 252,33 254,33 256,33 258,33 260,33 262,33 278,33 280,33 282,33 284,33 286,33 288,33 306,33 308,33 312,33 314,33 316,33 318,33 320,33 322,33 338,33 340,33 342,33 344,33 346,33 348,33 66,33.25 68,33.25 72,33.25 74,33.25 76,33.25 78,33.25 80,33.25 82,33.25 98,33.25 100,33.25 102,33.25 104,33.25 106,33.25 108,33.25 184.5,33.25 292.75,33.75 298.75,33.75 301.25,33.75 352.25,34.5 6,35 8,35 12,35 14,35 16,35 18,35 20,35 22,35 38,35 40,35 42,35 44,35 46,35 48,35 126,35 128,35 132,35 134,35 136,35 138,35 140,35 142,35 158,35 160,35 162,35 164,35 166,35 168,35 246,35 248,35 252,35 254,35 256,35 258,35 260,35 262,35 278,35 280,35 282,35 284,35 286,35 288,35 306,35 308,35 312,35 314,35 316,35 318,35 320,35 322,35 338,35 340,35 342,35 344,35 346,35 348,35 370.5,35 376.25,35 389.75,35 66,35.25 68,35.25 72,35.25 74,35.25 76,35.25 78,35.25 80,35.25 82,35.25 98,35.25 100,35.25 102,35.25 104,35.25 106,35.25 108,35.25 292.5,35.25 52.75,36 172.5,36 353.5,36.25 112.5,36.5 60.25,36.75 364,36.75 6,37 8,37 12,37 14,37 16,37 18,37 20,37 22,37 38,37 40,37 42,37 44,37 46,37 48,37 126,37 128,37 132,37 134,37 136,37 138,37 140,37 142,37 158,37 160,37 162,37 164,37 166,37 168,37 246,37 248,37 252,37 254,37 256,37 258,37 260,37 262,37 278,37 280,37 282,37 284,37 286,37 288,37 306,37 308,37 312,37 314,37 316,37 318,37 320,37 322,37 338,37 340,37 342,37 344,37 346,37 348,37 66,37.25 68,37.25 72,37.25 74,37.25 76,37.25 78,37.25 80,37.25 82,37.25 98,37.25 100,37.25 102,37.25 104,37.25 106,37.25 108,37.25 120.5,37.5 352.25,37.75 52.75,38.25 292.5,38.25 172.5,38.5 112.5,38.75 385.25,38.75 394.25,38.75 6,39 8,39 12,39 13.75,39 16,39 18,39 42,39 44,39 46,39 48,39 126,39 128,39 132,39 133.75,39 136,39 138,39 162,39 164,39 166,39 168,39 246,39 248,39 252,39 253.75,39 256,39 258,39 282,39 284,39 286,39 288,39 306,39 308,39 312,39 313.75,39 316,39 318,39 342,39 344,39 346,39 348,39 66,39.25 68,39.25 72,39.25 73.75,39.25 76,39.25 78,39.25 102,39.25 104,39.25 106,39.25 108,39.25 2,40 18,40.5 138,40.5 258,40.5 318,40.5 78,40.75 6,41 8,41 12,41 14,41 16,41 44,41 46,41 48,41 50,41 52.75,41 126,41 128,41 132,41 134,41 136,41 164,41 166,41 168,41 170,41 172.5,41 246,41 248,41 252,41 254,41 256,41 284,41 286,41 288,41 290,41 306,41 308,41 312,41 314,41 316,41 344,41 346,41 348,41 66,41.25 68,41.25 72,41.25 74,41.25 76,41.25 104,41.25 106,41.25 108,41.25 110,41.25 112.25,41.25 363.75,41.25 351.25,41.5 373,41.5 17.75,42 42,42 137.75,42 162,42 257.75,42 282,42 317.75,42 342,42 389.5,42 77.75,42.25 102,42.25 354,42.25 381.5,42.25 6,43 8,43 10,43 12,43 14,43 46,43 48,43 50,43 126,43 128,43 130,43 132,43 134,43 166,43 168,43 170,43 246,43 248,43 250,43 252,43 254,43 286,43 288,43 290,43 306,43 308,43 310,43 312,43 314,43 346,43 348,43 350,43 397,43 16.5,43.25 66,43.25 68,43.25 70,43.25 72,43.25 74,43.25 106,43.25 108,43.25 110,43.25 136.5,43.25 256.5,43.25 316.5,43.25 52.75,43.5 76.5,43.5 121.25,43.5 375,43.5 172.5,43.75 44,44 164,44 284,44 344,44 104,44.25 15.5,44.5 135.5,44.5 255.5,44.5 315.5,44.5 363.75,44.5 23.5,44.75 36.5,44.75 75.5,44.75 143.5,44.75 156.5,44.75 263.5,44.75 276.5,44.75 323.5,44.75 336.5,44.75 6,45 12,45 48,45 60.25,45 83.5,45 96.5,45 126,45 132,45 168,45 246,45 252,45 288,45 306,45 312,45 348,45 66,45.25 72,45.25 108,45.25 14.5,45.5 46,45.5 134.5,45.5 166,45.5 254.5,45.5 286,45.5 314.5,45.5 346,45.5 74.5,45.75 106,45.75 22.5,46 37.5,46 142.5,46 157.5,46 262.5,46 277.5,46 322.5,46 337.5,46 82.5,46.25 97.5,46.25 13.5,46.5 133.5,46.5 253.5,46.5 313.5,46.5 368.75,46.5 73.5,46.75 174.5,46.75 6,47 21.5,47 38.5,47 126,47 141.5,47 158.5,47 246,47 261.5,47 278.5,47 306,47 321.5,47 338.5,47 66,47.25 81.5,47.25 98.5,47.25 221,48 364.25,48.5 375,48.5 305,48.75 178,49 184,49.25 354,49.25 2,50 54,50 114.5,50 397,50 386,50.75 391,50.75 174.5,51 381.25,51 305,51.25 374.75,51.25 364.5,51.5 317.5,53.5 17.5,53.75 20,53.75 22.5,53.75 30,53.75 36.75,53.75 39.5,53.75 46.25,53.75 48.75,53.75 76.75,53.75 78.5,53.75 80.75,53.75 83,53.75 90,53.75 96.75,53.75 99.5,53.75 106,53.75 108.75,53.75 137,53.75 139.25,53.75 141.25,53.75 143.25,53.75 150,53.75 156.75,53.75 159,53.75 165.75,53.75 168.75,53.75 257,53.75 260,53.75 262.75,53.75 270,53.75 276.75,53.75 279.5,53.75 286,53.75 289,53.75 305,53.75 320,53.75 322.5,53.75 330,53.75 347.5,53.75 353.75,53.75 60.25,54 294.25,54 337,54 339.25,54 298.75,54.25 301.25,54.25 393.75,54.25 54,54.5 65.5,54.5 382.5,54.5 389.75,54.5 114.5,54.75 120,54.75 179.75,55 174.5,55.25 355,56.25 245.75,57 176.25,57.5 370.5,57.5 386.25,57.5 2,60 365.5,60 397,60 241.5,60.5 357,60.5 389.75,60.75 361.25,61 382.5,61 393.5,61.5 364,62.25 241,63.25 6.5,65 370,65.75 242.25,66 233.5,66.5 237.75,66.75 51,67 58.25,67 362.75,67.25 112.5,67.5 21.5,68.25 23.5,68.25 41.5,68.25 43.5,68.25 375.5,68.25 81.5,68.5 83.5,68.5 101.5,68.5 103.5,68.5 141.5,68.5 143.5,68.5 161.5,68.5 163.5,68.5 228.25,69 70.5,69.5 390,69.75 2,70 7.5,70 30,70 90,70 130,70 150,70 397,70 20,70.5 40,70.5 80,70.5 100,70.5 140,70.5 160,70.5 280,70.75 320,70.75 393.75,70.75 260,71 330,71.25 367.75,71.75 376,72 52.5,72.5 67.5,72.5 112.5,72.5 127.5,72.5 290,72.5 292.5,72.5 307.5,72.5 393.75,72.75 390.25,73 372.5,74 349.75,74.25 370.5,75 376,75 170,75.25 159,75.5 321,75.75 374.75,76 397,76 339.25,76.75 50,77.5 130,77.5 290,78 310,78 330,78.75 110,79 321,79.25 175.5,80.75 10,82 20,82 30,82 40,82 71,82 80,82 90,82 100,82 140,82 150,82 160,82 171,82 260,82 270,82 280,82 320,82 330,82 340,82 351,82 357,82 385,82 391.5,82.5 181,83 193,83 250,83
  other v2: 269.375,23.5 329.5,23.5 30.5,24.5 90.5,24.5 150.5,24.5 381,71 382.5,71 381,72.25 19.75,73.5 30,73.5 40.25,73.5 79.75,73.5 90,73.5 100.25,73.5 139.75,73.5 150,73.5 160.25,73.5 259.75,73.5 270,73.5 280.25,73.5 319.75,73.5 330,73.5 340.25,73.5 381,73.5 388.25,73.5 381,74.5 381,75.5 387,76.5 390.75,80.5
  other v3: 30,8.525 90,8.525 150,8.525 270,8.525 330,8.525 28.525,10 30,10 31.475,10 88.525,10 90,10 91.475,10 148.525,10 150,10 151.475,10 268.525,10 270,10 271.475,10 328.525,10 330,10 331.475,10 30,11.475 90,11.475 150,11.475 270,11.475 330,11.475 232.5,19.2 231.7,20 233.3,20 232.5,20.8 27.4,33.05 28.7,33.05 30,33.05 31.3,33.05 32.6,33.05 87.4,33.05 88.7,33.05 90,33.05 91.3,33.05 92.6,33.05 147.4,33.05 148.7,33.05 150,33.05 151.3,33.05 152.6,33.05 267.4,33.05 268.7,33.05 270,33.05 271.3,33.05 272.6,33.05 327.4,33.05 328.7,33.05 330,33.05 331.3,33.05 332.6,33.05 27.4,34.35 28.7,34.35 30,34.35 31.3,34.35 32.6,34.35 87.4,34.35 88.7,34.35 90,34.35 91.3,34.35 92.6,34.35 147.4,34.35 148.7,34.35 150,34.35 151.3,34.35 152.6,34.35 267.4,34.35 268.7,34.35 270,34.35 271.3,34.35 272.6,34.35 327.4,34.35 328.7,34.35 330,34.35 331.3,34.35 332.6,34.35 27.4,35.65 28.7,35.65 30,35.65 31.3,35.65 32.6,35.65 87.4,35.65 88.7,35.65 90,35.65 91.3,35.65 92.6,35.65 147.4,35.65 148.7,35.65 150,35.65 151.3,35.65 152.6,35.65 267.4,35.65 268.7,35.65 270,35.65 271.3,35.65 272.6,35.65 327.4,35.65 328.7,35.65 330,35.65 331.3,35.65 332.6,35.65 27.4,36.95 28.7,36.95 30,36.95 31.3,36.95 32.6,36.95 87.4,36.95 88.7,36.95 90,36.95 91.3,36.95 92.6,36.95 147.4,36.95 148.7,36.95 150,36.95 151.3,36.95 152.6,36.95 267.4,36.95 268.7,36.95 270,36.95 271.3,36.95 272.6,36.95 327.4,36.95 328.7,36.95 330,36.95 331.3,36.95 332.6,36.95 214.322,48.2 215.679,48.2 213.2,49.321 214.322,49.321 215.679,49.321 216.8,49.321 213.2,50.678 214.322,50.678 215.679,50.678 216.8,50.678 214.322,51.8 215.679,51.8 227.5,58.525 226.025,60 227.5,60 228.975,60 227.5,61.475 381.95,78.1 383.05,78.1 381.95,79.4 383.05,79.4
  other v4: 23.5,33.05 24.8,33.05 26.1,33.05 33.9,33.05 35.2,33.05 36.5,33.05 83.5,33.05 84.8,33.05 86.1,33.05 93.9,33.05 95.2,33.05 96.5,33.05 143.5,33.05 144.8,33.05 146.1,33.05 153.9,33.05 155.2,33.05 156.5,33.05 263.5,33.05 264.8,33.05 266.1,33.05 273.9,33.05 275.2,33.05 276.5,33.05 323.5,33.05 324.8,33.05 326.1,33.05 333.9,33.05 335.2,33.05 336.5,33.05 23.5,34.35 24.8,34.35 26.1,34.35 33.9,34.35 35.2,34.35 36.5,34.35 83.5,34.35 84.8,34.35 86.1,34.35 93.9,34.35 95.2,34.35 96.5,34.35 143.5,34.35 144.8,34.35 146.1,34.35 153.9,34.35 155.2,34.35 156.5,34.35 263.5,34.35 264.8,34.35 266.1,34.35 273.9,34.35 275.2,34.35 276.5,34.35 323.5,34.35 324.8,34.35 326.1,34.35 333.9,34.35 335.2,34.35 336.5,34.35 23.5,35.65 24.8,35.65 26.1,35.65 33.9,35.65 35.2,35.65 36.5,35.65 83.5,35.65 84.8,35.65 86.1,35.65 93.9,35.65 95.2,35.65 96.5,35.65 143.5,35.65 144.8,35.65 146.1,35.65 153.9,35.65 155.2,35.65 156.5,35.65 263.5,35.65 264.8,35.65 266.1,35.65 273.9,35.65 275.2,35.65 276.5,35.65 323.5,35.65 324.8,35.65 326.1,35.65 333.9,35.65 335.2,35.65 336.5,35.65 23.5,36.95 24.8,36.95 26.1,36.95 33.9,36.95 35.2,36.95 36.5,36.95 83.5,36.95 84.8,36.95 86.1,36.95 93.9,36.95 95.2,36.95 96.5,36.95 143.5,36.95 144.8,36.95 146.1,36.95 153.9,36.95 155.2,36.95 156.5,36.95 263.5,36.95 264.8,36.95 266.1,36.95 273.9,36.95 275.2,36.95 276.5,36.95 323.5,36.95 324.8,36.95 326.1,36.95 333.9,36.95 335.2,36.95 336.5,36.95 381.95,76.8 383.05,76.8 381.95,80.7 383.05,80.7
  other v5: 30,42 150,42 270,42 330,42 90,42.25 30,47.25 150,47.25 270,47.25 330,47.25 90,47.5 30,49 150,49 270,49 330,49 90,49.25 30,51 150,51 270,51 330,51 90,51.25
  other v6: 4,4 120,4 300,4 396,4 212.25,41 120,70 300,70 4,81 396,81
GND-IO: C710.2 C711.2 C712.2 C713.1 C714.1 C715.1 C716.1 C717.1 C718.1 C719.1 C720.1 C721.1 C722.1 C723.1 C724.1 C725.1 C726.1 C732.1 C733.1 C734.1 C735.1 C736.1 C747.1 C748.1 C749.1 C750.1 C751.1 C757.1 C758.1 C759.1 C760.1 C761.1 C762.1 C763.1 C764.1 C765.1 C766.1 CENTER-TWEETER.2 CENTER-TWEETER.3 CENTER-WOOFER.2 CENTER-WOOFER.3 FL-TWEETER.2 FL-TWEETER.3 FL-WOOFER.2 FL-WOOFER.3 FR-TWEETER.2 FR-TWEETER.3 FR-WOOFER.2 FR-WOOFER.3 J700.1 J700.3 J700.5 J700.7 J700.9 J700.11 J700.13 J700.15 J700.17 J700.19 J700.21 J700.23 J700.25 J700.27 J700.29 J700.31 J700.33 J700.35 J700.37 J700.39 J700.41 J700.43 J700.45 J700.47 J700.49 R742.2 R743.2 R744.1 R745.1 R746.1 R747.1 R748.1 R749.1 R750.1 R751.1 R752.1 R753.1 R754.2 SURROUND-LEFT.2 SURROUND-LEFT.3 SURROUND-RIGHT.2 SURROUND-RIGHT.3 U700.4 U701.4 U702.4 U703.4 U704.4 U705.4 U706.4 U707.4 U708.4 U709.4 UPMIX-LEFT.2 UPMIX-LEFT.3 UPMIX-RIGHT.2 UPMIX-RIGHT.3
INA1: J2.12 JP100.3 | length 189.6
  Bottom Copper w0.25: JP100.3@47.46,18.75 49.21,20.5 53,20.5 55.25,22.75 55.25,61.5 61.5,67.75 109.75,67.75 112.5,65 122.5,65 125.25,67.75 190.05,67.75 J2.12@191.27,66.53
INA2: J2.20 JP200.3 | length 116.9
  Bottom Copper w0.25: JP200.3@107.46,18.75 115,26.29 115,47.5 130,62.5 182.5,62.5 187.5,57.5 190.14,57.5 J2.20@191.27,56.37
INA3: J2.28 JP300.3 | length 45.9
  Bottom Copper w0.25: JP300.3@167.25,18.75 JP300.3@167.355,18.855 ; JP300.3@167.46,18.75 173.75,25.04 173.75,41.25 180,47.5 189.98,47.5 J2.28@191.27,46.21
INA4: J2.36 JP400.3 | length 215.3
  Bottom Copper w0.25: J2.36@191.27,36.05 193.25,38.03 193.25,77.5 198.25,82.5 242.5,82.5 250,75 250,70 252.5,67.5 293.75,67.5 297.5,63.75 297.5,20 294.25,16.75 289.46,16.75 JP400.3@287.46,18.75
INA5: J2.44 JP500.3 | length 273.2
  Top Copper w0.25: v2(215,77.5) 216.5,77.5 217,77 221,77 223,75 229,75 230,76 244,76 247.5,72.5 247.5,65 v2(250,62.5) ; v2(292.5,63.75) 302.5,63.75 v2(303.75,62.5)
  Bottom Copper w0.25: J2.44@191.27,25.89 197.19,31.81 197.19,34.19 198.25,35.25 198.25,73.25 202.5,77.5 v2(215,77.5) ; v2(250,62.5) 290,62.5 291.25,63.75 v2(292.5,63.75) ; v2(303.75,62.5) 350,62.5 356.25,56.25 356.25,18.75 354,16.5 349.71,16.5 JP500.3@347.46,18.75
INB1: J2.14 JP101.3 | length 201.8
  Bottom Copper w0.25: JP101.3@37.46,18.75 39.21,17 54,17 56.5,19.5 56.5,60.25 62.5,66.25 108.75,66.25 111.25,63.75 123.75,63.75 126.25,66.25 186.25,66.25 187.485,65.015 190.245,65.015 J2.14@191.27,63.99
INB2: J2.22 JP201.3 | length 132.1
  Bottom Copper w0.25: JP201.3@97.5,18.75 99.75,16.5 113.5,16.5 116.25,19.25 116.25,46.25 131.25,61.25 181.25,61.25 187.5,55 190.1,55 J2.22@191.27,53.83
INB3: J2.30 JP301.3 | length 60.1
  Bottom Copper w0.25: JP301.3@157.46,18.75 159.46,16.75 174.25,16.75 175,17.5 175,40 180,45 189.94,45 J2.30@191.27,43.67
INB4: J2.38 JP401.3 | length 218.4
  Bottom Copper w0.25: J2.38@191.27,33.51 193.255,35.495 193.255,36.255 194.5,37.5 194.5,76.5 199.25,81.25 241.25,81.25 247.5,75 247.5,70 251.25,66.25 292.5,66.25 296.25,62.5 296.25,23.75 293.5,21 279.71,21 JP401.3@277.46,18.75
INB5: J2.46 JP501.3 | length 274.7
  Top Copper w0.25: v2(215,76.25) 216.125,76.25 216.75,75.625 220.875,75.625 222.875,73.625 229.625,73.625 230.875,74.875 242,74.875 246.25,70.625 246.25,63.75 v2(247.5,62.5) ; v2(293.75,62) 301.125,62 v2(301.875,61.25)
  Bottom Copper w0.25: J2.46@191.27,23.35 198.71,30.79 198.71,33.46 199.5,34.25 199.5,72 203.75,76.25 v2(215,76.25) ; v2(247.5,62.5) 248.75,61.25 291.25,61.25 292,62 v2(293.75,62) ; v2(301.875,61.25) 348.75,61.25 355,55 355,23.75 352.25,21 339.71,21 JP501.3@337.46,18.75
INC1: J2.16 JP102.3 | length 223.5
  Bottom Copper w0.25: JP102.3@17.46,18.75 19.46,20.75 30.75,20.75 35.75,15.75 54.75,15.75 57.75,18.75 57.75,57.75 65,65 107,65 109.5,62.5 125,62.5 127.5,65 185,65 187.5,62.5 190.22,62.5 J2.16@191.27,61.45
INC2: J2.24 JP202.3 | length 154.4
  Bottom Copper w0.25: JP202.3@77.46,18.75 79.46,20.75 92.5,20.75 98,15.25 114,15.25 117.5,18.75 117.5,45 132.5,60 180,60 187.5,52.5 190.06,52.5 J2.24@191.27,51.29
INC3: J2.32 JP302.3 | length 81.5
  Bottom Copper w0.25: JP302.3@137.46,18.75 139.71,21 152.5,21 156.25,17.25 156.75,16.75 158,16.75 159.25,15.5 174.75,15.5 176.5,17.25 176.5,39 180,42.5 189.9,42.5 J2.32@191.27,41.13
INC4: J2.40 JP402.3 | length 168.2
  Top Copper w0.25: v2(203.75,80) 206.25,82.5 237.25,82.5 v2(241.25,78.5)
  Bottom Copper w0.25: J2.40@191.27,30.97 194.5,34.2 194.5,35.75 195.75,37 195.75,75.5 200.25,80 v2(203.75,80) ; v2(241.25,78.5) 245.75,74 245.75,63.25 243.75,61.25 243.75,26.25 247.5,22.5 253.71,22.5 JP402.3@257.46,18.75
INC5: J2.48 JP502.3 | length 219.3
  Top Copper w0.25: v2(215,75) 216.25,73.75 221.25,73.75 222.5,72.5 230.75,72.5 231.875,73.625 240.125,73.625 244.5,69.25 244.5,63 v2(247.5,60) ; v2(292.5,60) v2(300,60)
  Bottom Copper w0.25: J2.48@191.27,20.81 199.98,29.52 199.98,32.48 200.75,33.25 200.75,70.75 205,75 v2(215,75) ; v2(247.5,60) v2(292.5,60) ; v2(300,60) 301.25,60 302.5,58.75 302.5,26.25 307.75,21 315.21,21 JP502.3@317.46,18.75
IND1: J2.18 JP103.3 | length 233.5
  Bottom Copper w0.25: JP103.3@7.46,18.75 9.46,16.75 30.75,16.75 33,14.5 55.75,14.5 59,17.75 59,56.5 66,63.5 105,63.5 108.5,60 125,60 128.625,63.625 184.125,63.625 187.75,60 190.18,60 J2.18@191.27,58.91
IND2: J2.26 JP203.3 | length 165.2
  Bottom Copper w0.25: JP203.3@67.46,18.75 69.46,16.75 84.25,16.75 86.25,18.75 93,18.75 97.75,14 114.75,14 118.75,18 118.75,43.75 133.75,58.75 178.75,58.75 187.5,50 190.02,50 J2.26@191.27,48.75
IND3: J2.34 JP303.3 | length 88.5
  Bottom Copper w0.25: JP303.3@127.46,18.75 128.5,18.75 128.85,18.4 128.85,18.274 129.524,17.6 129.65,17.6 130.25,17 154.5,17 156,15.5 157.75,15.5 159,14.25 175.5,14.25 177.875,16.625 177.875,36.625 181,39.75 190.11,39.75 J2.34@191.27,38.59
IND4: J2.42 JP403.3 | length 159.1
  Top Copper w0.25: v2(217.5,78.75) 220,81.25 236.25,81.25 v2(240,77.5)
  Bottom Copper w0.25: J2.42@191.27,28.43 196,33.16 196,35.25 197,36.25 197,74.5 201.25,78.75 v2(217.5,78.75) ; v2(240,77.5) 244.25,73.25 244.25,63.5 242.5,61.75 242.5,23.71 JP403.3@247.46,18.75
IND5: J2.50 JP503.3 | length 207
  Top Copper w0.25: v2(211,73.75) 213.5,71.25 221.5,71.25 221.625,71.375 236.125,71.375 240,67.5 240,62.5 241.25,61.25 243.75,61.25 v2(245,60) ; v2(293.75,57.5) v2(300,57.5)
  Bottom Copper w0.25: J2.50@191.27,18.27 201.5,28.5 201.5,31.75 202,32.25 202,69.5 206.25,73.75 v2(211,73.75) ; v2(245,60) 247.5,57.5 v2(293.75,57.5) ; v2(300,57.5) 300,26.21 JP503.3@307.46,18.75
INPUTA1: C118.1 R102.2 U101.18 | length 17.6
  Top Copper w0.25: U101.18@34.128,31.2 34.128,29.623 34.875,28.875 34.875,25.125 35.75,24.25 42.05,24.25 R102.2@43.8,22.5 C118.1@43.8,21.25
INPUTA2: C218.1 R202.2 U201.18 | length 17.6
  Top Copper w0.25: U201.18@94.128,31.2 94.128,29.623 94.875,28.875 94.875,25.125 95.75,24.25 102.05,24.25 R202.2@103.8,22.5 C218.1@103.8,21.25
INPUTA3: C318.1 R302.2 U301.18 | length 17.6
  Top Copper w0.25: U301.18@154.127,31.2 154.127,29.623 154.875,28.875 154.875,25.125 155.75,24.25 162.05,24.25 R302.2@163.8,22.5 C318.1@163.8,21.25
INPUTA4: C418.1 R402.2 U401.18 | length 17.6
  Top Copper w0.25: U401.18@274.128,31.2 274.128,29.623 275,28.75 275,25 275.75,24.25 282.05,24.25 R402.2@283.8,22.5 C418.1@283.8,21.25
INPUTA5: C518.1 R502.2 U501.18 | length 17.6
  Top Copper w0.25: U501.18@334.128,31.2 334.128,29.623 334.875,28.875 334.875,25.125 335.75,24.25 342.05,24.25 R502.2@343.8,22.5 C518.1@343.8,21.25
INPUTB1: C125.1 R106.2 U101.17 | length 10.1
  Top Copper w0.25: U101.17@33.493,31.2 33.493,29.008 33.75,28.75 33.75,22.55 R106.2@33.8,22.5 C125.1@33.8,21.25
